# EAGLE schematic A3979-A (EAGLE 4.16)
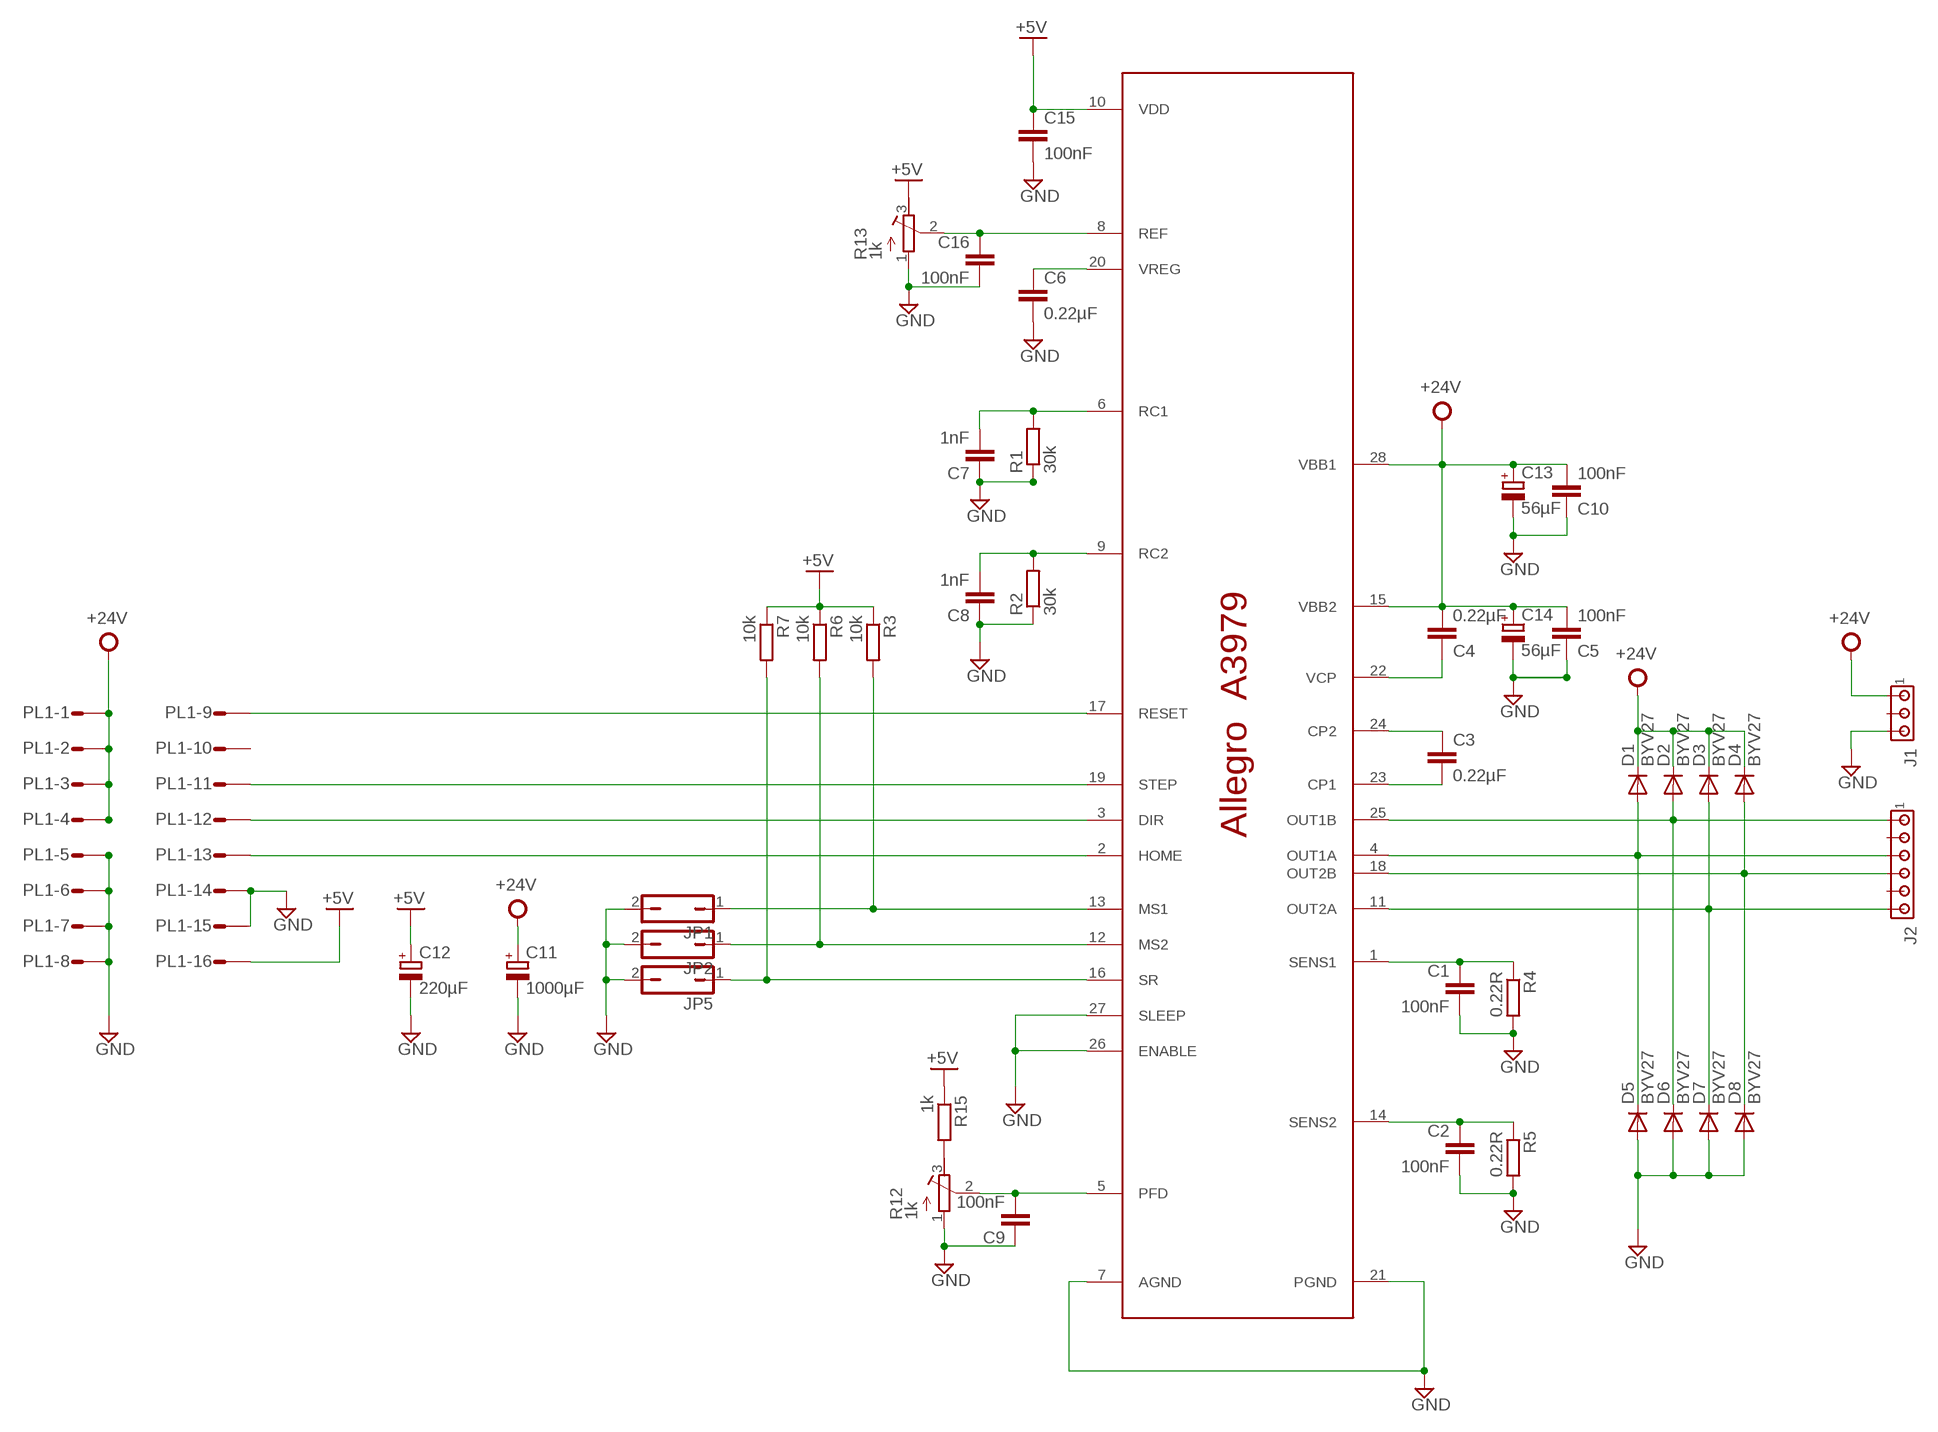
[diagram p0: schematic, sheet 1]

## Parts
C1  100nF  C-EU025-040X050  [C025-040X050]
C2  100nF  C-EU025-040X050  [C025-040X050]
C3  0.22µF  C-EU050-035X075  [C050-035X075]
C4  0.22µF  C-EU050-035X075  [C050-035X075]
C5  100nF  C-EU025-040X050  [C025-040X050]
C6  0.22µF  C-EU050-035X075  [C050-035X075]
C7  1nF  C-EU025-030X050  [C025-030X050]
C8  1nF  C-EU025-030X050  [C025-030X050]
C9  100nF  C-EU025-040X050  [C025-040X050]
C10  100nF  C-EU025-040X050  [C025-040X050]
C11  1000µF  CPOL-EUE5-13  [E5-13]
C12  220µF  CPOL-EUE2.5-6  [E2,5-6]
C13  56µF  CPOL-EUE2.5-6  [E2,5-6]
C14  56µF  CPOL-EUE2.5-6  [E2,5-6]
C15  100nF  C-EU025-040X050  [C025-040X050]
C16  100nF  C-EU025-040X050  [C025-040X050]
D1  BYV27  [SOD57-10]
D2  BYV27  [SOD57-10]
D3  BYV27  [SOD57-10]
D4  BYV27  [SOD57-10]
D5  BYV27  [SOD57-10]
D6  BYV27  [SOD57-10]
D7  BYV27  [SOD57-10]
D8  BYV27  [SOD57-10]
J1  MTA03-100  [10X03MTA]
J2  MTA06-100  [10X06MTA]
JP1  JP1Q  [JP1]
JP2  JP1Q  [JP1]
JP5  JP1Q  [JP1]
PL1  16HS  [16H]
R1  30k  R-EU_0204/2V  [0204V]
R2  30k  R-EU_0204/2V  [0204V]
R3  10k  R-EU_0204/2V  [0204V]
R4  0.22R  R-EU_0617/22  [0617/22]
R5  0.22R  R-EU_0617/22  [0617/22]
R6  10k  R-EU_0204/2V  [0204V]
R7  10k  R-EU_0204/2V  [0204V]
R12  1k  R-TRIMM64W  [RTRIM64W]
R13  1k  R-TRIMM64W  [RTRIM64W]
R15  1k  R-EU_0204/2V  [0204V]
U$1  A3979  [TSSOP28]

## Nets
+5V: C12.+ C15.1 PL1.16 R3.1 R6.1 R7.1 R13.3(A) R15.1 U$1.10(VDD)
+24V: C4.2 C5.2 C10.2 C11.+ C13.+ C14.+ D1.C D2.C D3.C D4.C J1.1 PL1.1 PL1.2 PL1.3 PL1.4 U$1.15(VBB2) U$1.28(VBB1)
GND: C1.2 C2.2 C5.1 C6.2 C7.1 C8.1 C9.1 C10.1 C11.- C12.- C13.- C14.- C15.2 C16.2 D5.A D6.A D7.A D8.A J1.3 JP1.2 JP2.2 JP5.2 PL1.5 PL1.6 PL1.7 PL1.8 PL1.14 PL1.15 R1.1 R2.1 R4.2 R5.2 R12.1(E) R13.1(E) U$1.7(AGND) U$1.21(PGND) U$1.26(ENABLE) U$1.27(SLEEP)
N$1: PL1.12 U$1.3(DIR)
N$2: C3.2 U$1.23(CP1)
N$3: PL1.13 U$1.2(HOME)
N$4: C2.1 R5.1 U$1.14(SENS2)
N$5: D1.A D5.C J2.3 U$1.4(OUT1A)
N$6: D2.A D6.C J2.1 U$1.25(OUT1B)
N$7: D3.A D7.C J2.6 U$1.11(OUT2A)
N$8: D4.A D8.C J2.4 U$1.18(OUT2B)
N$9: C3.1 U$1.24(CP2)
N$10: JP1.1 R3.2 U$1.13(MS1)
N$11: C1.1 R4.1 U$1.1(SENS1)
N$12: JP2.1 R6.2 U$1.12(MS2)
N$13: C6.1 U$1.20(VREG)
N$14: C16.1 R13.2(S) U$1.8(REF)
N$16: JP5.1 R7.2 U$1.16(SR)
N$18: C8.2 R2.2 U$1.9(RC2)
N$19: C4.1 U$1.22(VCP)
N$20: C7.2 R1.2 U$1.6(RC1)
N$21: C9.2 R12.2(S) U$1.5(PFD)
N$22: PL1.11 U$1.19(STEP)
N$23: PL1.9 U$1.17(RESET)
N$25: R12.3(A) R15.2
Unconnected: J1.2 J2.2 J2.5 PL1.10

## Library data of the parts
C1 C2 C5 C9 C10 C15 C16 = rcl-2:C-EU: CAPACITOR, European symbol
C3 C4 C6-C8 = rcl:C-EU: CAPACITOR, European symbol
C11-C14 = rcl:CPOL-EU: POLARIZED CAPACITOR, European symbol
D1-D8 = diode:BYV27: DIODE
J1 = con-amp:MTA03-100: AMP connector
J2 = con-amp:MTA06-100: AMP connector
JP1 JP2 JP5 = jumper:JP1Q: JUMPER
PL1 = con-harting-h:16HS: CONNECTOR
R1-R7 R15 = rcl-2:R-EU_: RESISTOR, European symbol
R12 R13 = rcl-2:R-TRIMM: Trimm resistor
U$1 = untitled:A3979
